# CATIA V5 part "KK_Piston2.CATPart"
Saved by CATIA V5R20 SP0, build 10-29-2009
Part number: Piston2
Bounding box of the stored display mesh (mm): x 15.005 to 43.198, y 56.674 to 81.941, z 33.876 to 105
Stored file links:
  G:\Khaled_CFAO_2011\ST2M\ST2M_GR1\msallin\Khaled\Version_Finale\KK_Piston2.CATPart
  C:\Users\Mathieu\Desktop\Think Motion\JOUG-MELEE2.CATProduct
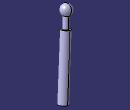
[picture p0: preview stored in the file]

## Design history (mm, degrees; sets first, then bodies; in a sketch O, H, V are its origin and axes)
External parameters (linked from other documents)
  `External.Taille du joug` = 100 mm
Set1
  Line1: linked copy from another document
  Line2: linked copy from another document
  Point1: linked copy from another document
Set2
  Plane1: type 2Lines, Element1 Line1, Element2 Line2
Body1 (main body)
  Sketch1 on Plane1, origin (65.2773, 37.9842, 28.9253), H (0.5029, -0.8643, 0), V (-0.3091, -0.1799, 0.9339)
    point P1 (-47.6097, 6.9165)
    line L1 (-47.6097, 6.9165) -> (-51.7681, 7.1789)
    line L2 (-51.7681, 7.1789) -> (-48.3053, 62.0698)
    line L3 (-48.3053, 62.0698) -> (-46.6419, 61.9648)
    line L4 (-46.6419, 61.9648) -> (-46.0123, 71.945)
    arc A1 centre (-43.2446, 76.1091) radius 5 from (-42.9298, 81.0992) to (-46.0123, 71.945) ccw
    point P6 (-43.2446, 76.1091)
    point P7 (-42.9298, 81.0992)
    reference projected line E1 (-43.2446, 76.1091) -> (-50, -30.9742) from Line1
    reference projected line E2 (-43.2446, 76.1091) -> (-50, -30.9742) from Line1
    reference projected line E3 (-43.2446, 76.1091) -> (-50, -30.9742) from Line1
    reference projected point E4 (-43.2446, 76.1091) from Point1
    reference projected line E5 (-43.2446, 76.1091) -> (-50, -30.9742) from Line1
    distance L2 E1 = 4.1667 {= `External.Taille du joug` /24}
    distance P1 E2 = 0
    length L2 = 55 {= `External.Taille du joug` *(7/10-1/10-1/20)}
    length L4 = 10 {= `External.Taille du joug` /10}
    distance L4 E3 = 2.5 {= `External.Taille du joug` /40}
    radius A1 = 5 {= `External.Taille du joug` /20}
    distance P6 E4 = 0
    distance E5 P7 = 0
    perpendicularity: L2 L1
    parallelism: L3 L1, L4 L2
  Shaft1: profile Sketch1, axis Line1, angle 360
